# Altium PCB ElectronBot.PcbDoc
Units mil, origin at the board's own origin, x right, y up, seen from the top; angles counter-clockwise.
Board outline 1479.69 x 1548.74 mil, 2 copper layers (Top1, Bottom2), stack 42.17 mil thick; 69 components, 72 nets, 328 pads, 93 vias.
Unrouted connection lines stored in the file: 11.
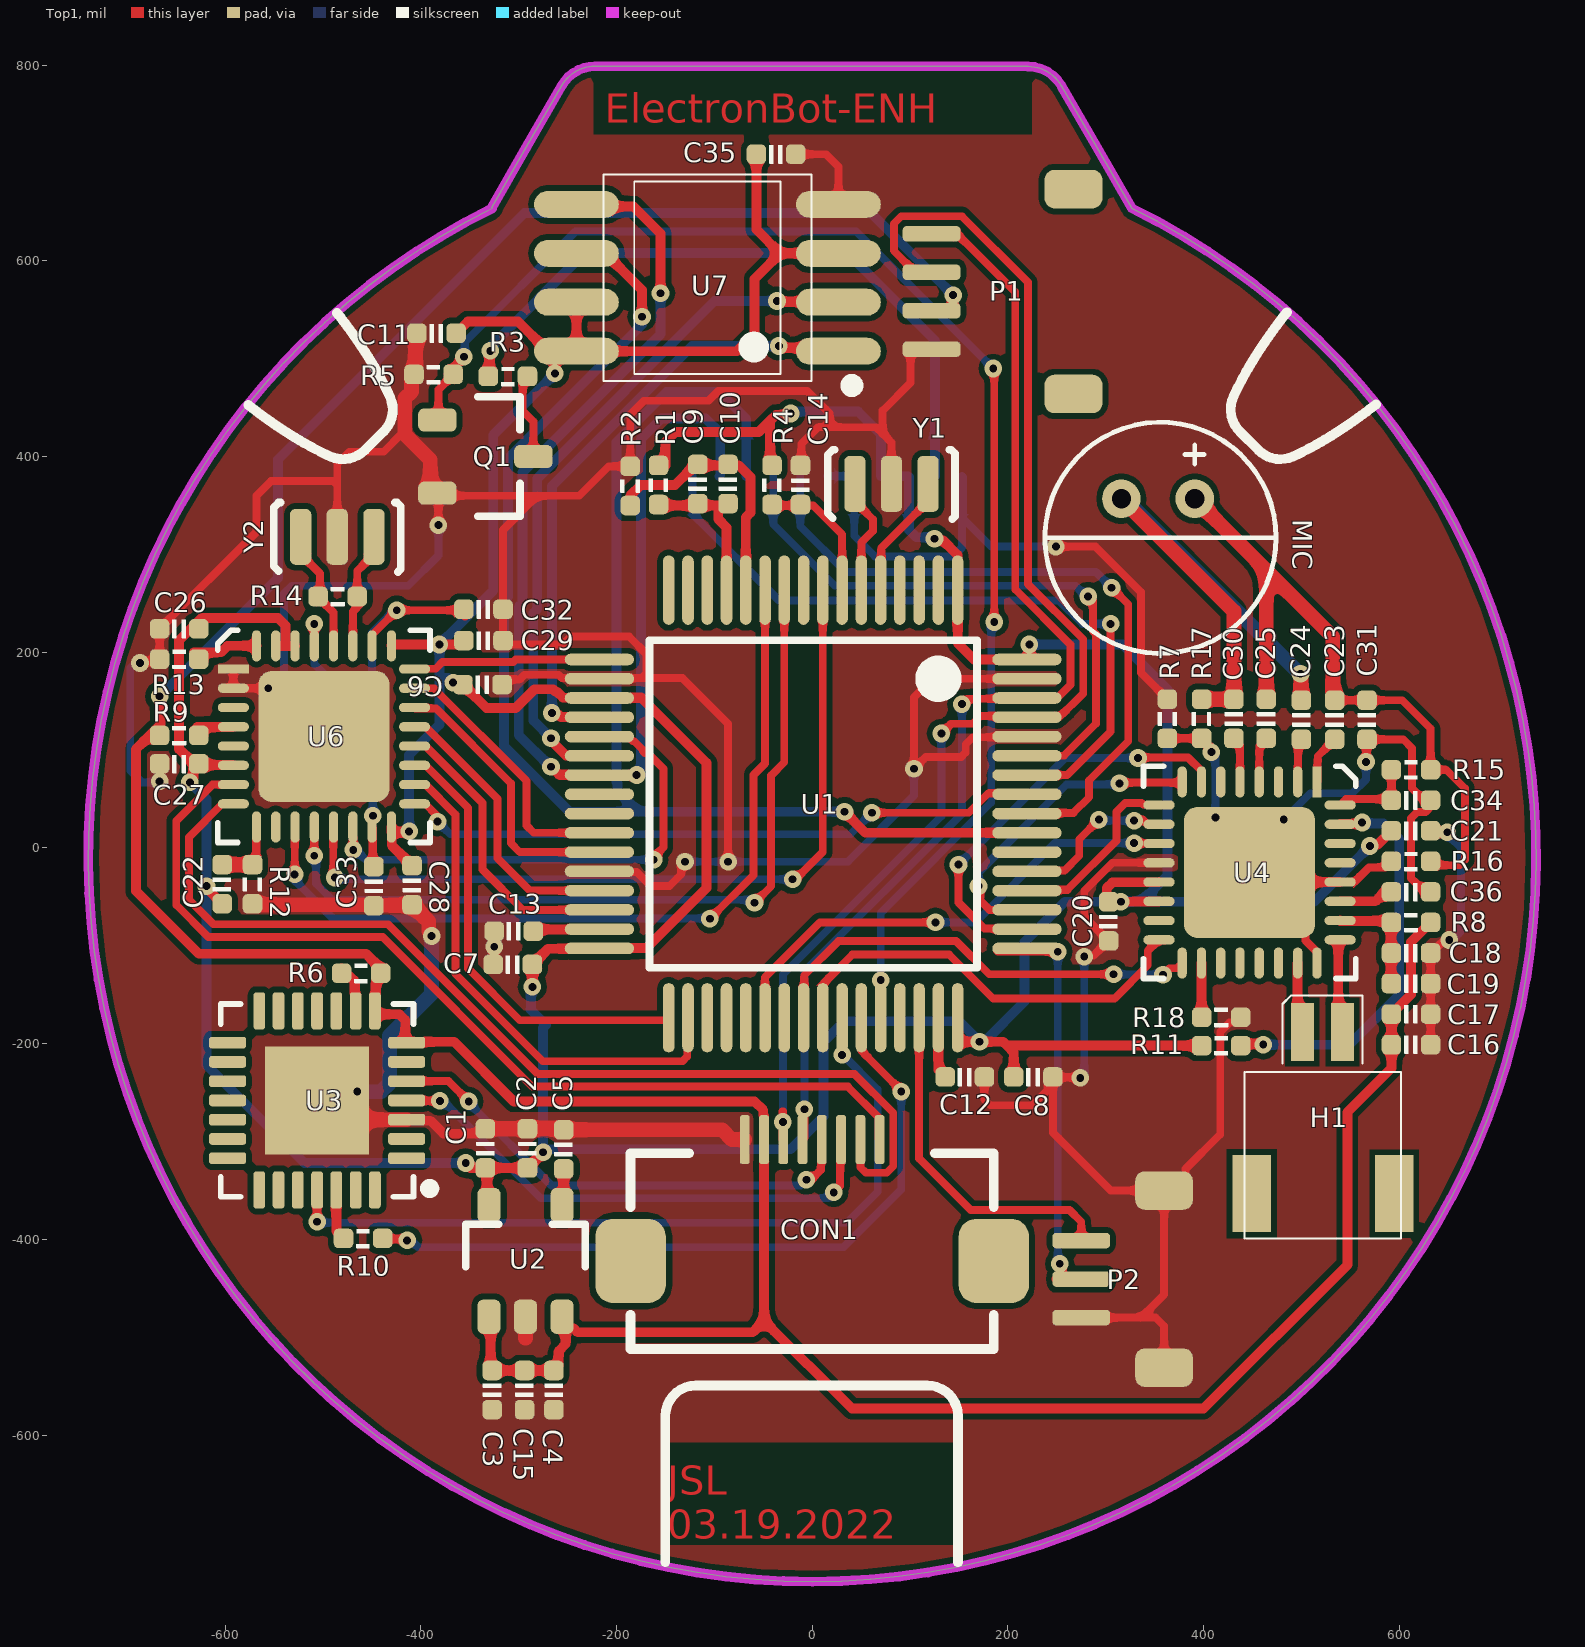
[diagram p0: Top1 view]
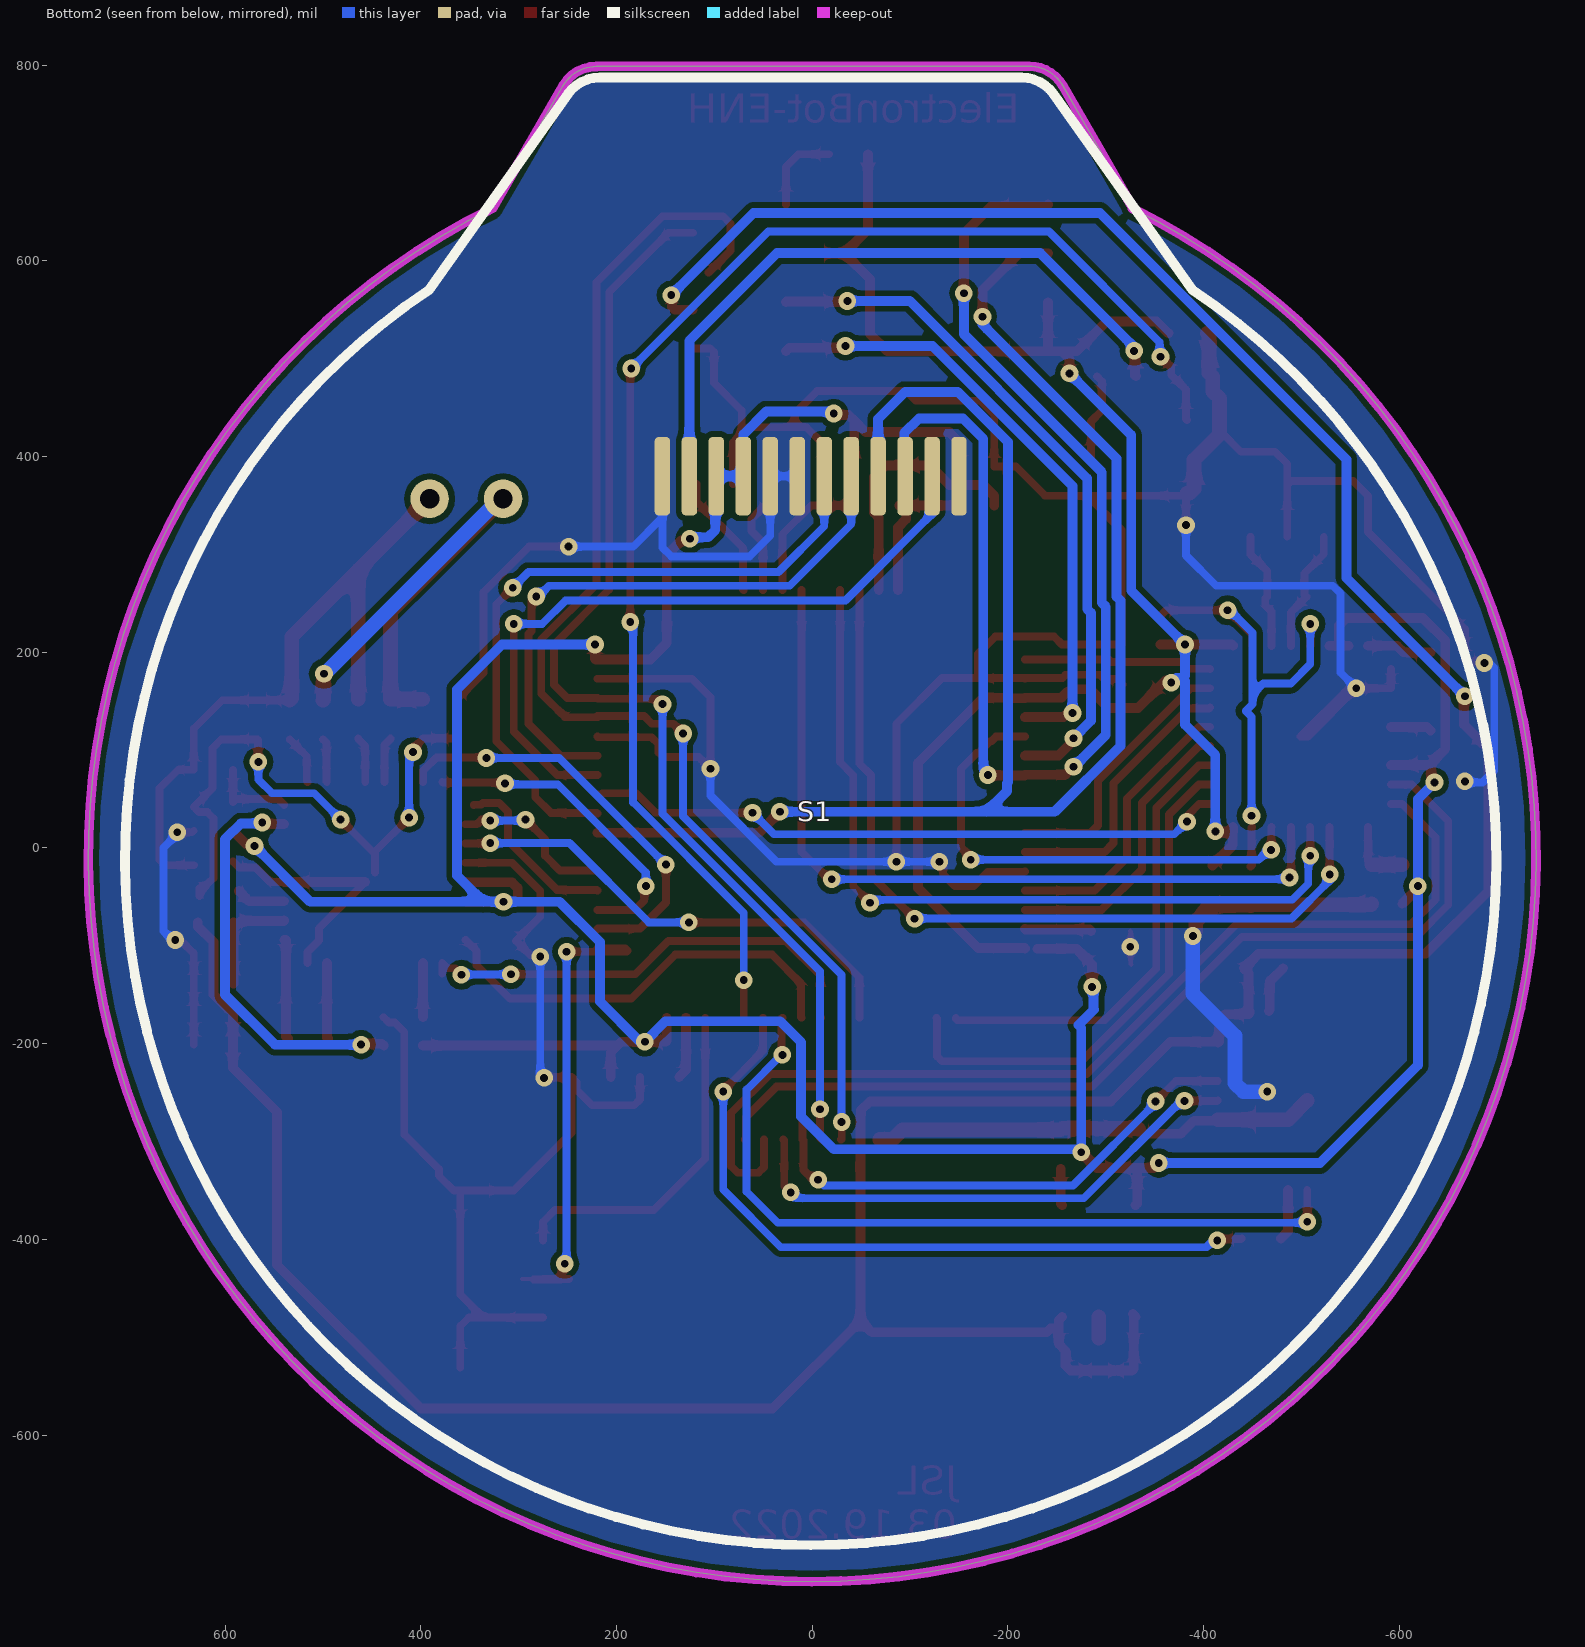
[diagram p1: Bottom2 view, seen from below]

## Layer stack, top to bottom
Top Solder: solder mask 0.4, Solder Resist, Dk 3.5
Top1: signal copper 1.4
Dielectric 1: prepreg 39.3701, PP-006, Dk 4.1
Bottom2: signal copper 1.4
Bottom Solder: solder mask 0.4, Solder Resist, Dk 3.5

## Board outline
-327.58,654.33 -292.13,716.15 -256.03,779.09 cw(c-221.88,759.5) -221.87,798.87 220.56,798.71 cw(c220.54,759.34) 254.64,779.01 290.88,716.22 326.65,654.22 326.51,653.93 cw(c0,-10)

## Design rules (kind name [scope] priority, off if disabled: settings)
Clearance Clearance_Logo [InNetClass('Logo')] p1: gap=8 ignorepadtopadclearanceinfootprint=FALSE
Clearance [All] p2: gap=5 ignorepadtopadclearanceinfootprint=FALSE
ComponentClearance [All] p1: gap=0 collisioncheckmode=3 verticalgap=0 showdistances=FALSE
DiffPairsRouting [All] p1: maxlimit=9 minlimit=9 mostfreqgap=9 toplayer_minwidth=15 toplayer_maxwidth=15 toplayer_prefwidth=15 bottomlayer_minwidth=15 bottomlayer_maxwidth=15 bottomlayer_prefwidth=15 maxuncoupledlength=500
FanoutControl Fanout_BGA [All] p1: bgadir=Out bgaviamode=Centered fanoutstyle=Auto fanoutdirection=Alternating viagrid=1 // Fanout_BGA (Default Rule)
HoleSize [All] p1: absolutevalues=TRUE maxlimit=10000 minlimit=8 maxpercent=80.000 minpercent=20.000
MinimumSolderMaskSliver [All] p1 off: minsoldermaskwidth=2
PlaneClearance [All] p1: clearance=8
PlaneConnect [All] p1: planeconnectstyle=Direct reliefexpansion=20 reliefentries=4 reliefconductorwidth=10 reliefairgap=10
PolygonConnect [All] p1: connectstyle=Direct reliefconductorwidth=10 reliefentries=4 polygonreliefangle="90 Angle" airgapwidth=10
RoutingVias [All] p1: holewidth=8 width=16 viastyle="Through Hole" minholewidth=6 minwidth=12 maxholewidth=28 maxwidth=50
SilkToSilkClearance [All] p1: silktosilkclearance=0
SilkToSolderMaskClearance [IsPad] p1: minsilkscreentomaskgap=0 clearancetoexposedcopper=TRUE
SolderMaskExpansion [All] p1: expansion=3
Width Logo [InNetClass('Logo')] p1: maxlimit=100 minlimit=0.1 preferedwidth=10
Width GND [(InNet('AGND') OR InNet('GND'))] p2: maxlimit=50 minlimit=4 preferedwidth=10
Width VCC [(InNet('VDD_SYS_3.3V') OR InNet('VDD_AV_3.3V') OR InNet('VDD_5V') OR InNet('VDD1V2-SYS') OR InNet('VDD1V1-EPHY') OR InNet('VDD-CPUX') OR InNet('VDD-CPUS') OR InNet('VDD-CPUFB') OR InNet('VCC-DRAM'))] p3: maxlimit=50 minlimit=4 preferedwidth=10
Width [All] p4: maxlimit=10000 minlimit=4 preferedwidth=4
21 further rules are at their usual default settings.

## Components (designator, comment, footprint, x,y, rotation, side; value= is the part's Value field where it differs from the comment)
C1 "0.1uF" CAP_0402 -334,-307 r270 top value=0.1u
C2 "10uF" CAP_0402 -291,-307 r270 top value=0.1u
C3 "10uF" CAP_0402 -327,-554 r90 top value=0.1u
C4 "0.1uF" CAP_0402 -264,-554 r90 top value=0.1u
C5 "10nF" CAP_0402 -254,-308 r270 top value=0.1u
C6 "0.1uF" CAP_0402 -337,167 r180 top value=0.1u
C7 "0.1uF" CAP_0402 -306,-119 r0 top value=0.1u
C8 "0.1uF" CAP_0402 226,-234 r180 top value=0.1u
C9 "0.1uF" CAP_0402 -117,372 r270 top value=0.1u
C10 "10uF" CAP_0402 -86,372 r270 top value=0.1u
C11 "0.1uF" CAP_0402 -384,526 r0 top value=0.1u
C12 "10uF" CAP_0402 156,-234 r180 top value=0.1u
C13 "10uF" CAP_0402 -305,-85 r0 top value=0.1u
C14 "0.1uF" CAP_0402 -12,371 r270 top value=0.1u
C15 "10uf" CAP_0402 -294,-554 r270 top value=0.1u
C16 "10uf" CAP_0402 612,-201 r0 top value=0.1u
C17 "0.1uF" CAP_0402 612,-169.78 r0 top value=0.1u
C18 "10uf" CAP_0402 612,-107.33 r180 top value=0.1u
C19 "0.1uF" CAP_0402 612,-138.56 r180 top value=0.1u
C20 "10uf" CAP_0402 303,-75 r90 top value=0.1u
C21 "0.1uF" CAP_0402 612,17.56 r180 top value=0.1u
C22 "10nF" CAP_0402 -603,-37 r90 top value=0.1u
C23 "1uF" CAP_0402 534,131 r90 top value=0.1u
C24 "1uF" CAP_0402 500,131 r90 top value=0.1u
C25 "1uF" CAP_0402 464,132 r90 top value=0.1u
C26 "0.1uF" CAP_0402 -647,224 r180 top value=0.1u
C27 "0.1uF" CAP_0402 -647,86 r180 top value=0.1u
C28 "0.1uF" CAP_0402 -409,-38 r270 top value=0.1u
C29 "0.1uF" CAP_0402 -336,212 r0 top value=0.1u
C30 "1uF" CAP_0402 431,132 r90 top value=0.1u
C31 "220pf" CAP_0402 567,131 r90 top value=0.1u
C32 "10uF" CAP_0402 -336,244 r0 top value=0.1u
C33 "0.1uF" CAP_0402 -448,-39 r270 top value=0.1u
C34 "10uF" CAP_0402 612,48.78 r0 top value=0.1u
C35 "0.1uF" CAP_0402 -37,709 r0 top value=0.1u
C36 "10uF" CAP_0402 612,-44.89 r0 top value=0.1u
CON1 "FFC_0.5_8" FFC_0.5_8 0,-387 r0 top
H1 "HEADER-2P" header2p_1.0 521.96,-309.06 r0 top
MIC "MIC" MIC6*2.2 356,317 r0 top (schematic designator U5)
P1 "SH1.0-4P" SH1.0-4P 122,568.69 r90 top
P2 "SH1.0-3P-STAND" SH1.0-3P-STAND 275,-440.63 r90 top
Q1 "AO3400A" SOT23-3 -334,400 r0 top
R1 "0R" RES_0402 -157,371 r90 top value=22R
R2 "0R" RES_0402 -186,370 r90 top value=22R
R3 "10R" RES_0402 -311,482 r180 top value=22R
R4 "10K" RES_0402 -41,371 r90 top value=22R
R5 "10K" RES_0402 -387,484 r0 top value=22R
R6 "10K" RES_0402 -461,-128 r180 top value=22R
R7 "0R" RES_0402 363,132 r90 top value=22R
R8 "0R" RES_0402 612,-76.11 r0 top value=22R
R9 "0R" RES_0402 -647,115 r0 top value=22R
R10 "200R" RES_0402 -459,-399 r180 top value=22R
R11 "0R" RES_0402 418,-202 r180 top value=22R
R12 "10K" RES_0402 -572,-37 r270 top value=22R
R13 "12K" RES_0402 -647,193 r180 top value=22R
R14 "1M" RES_0402 -485,257 r0 top value=22R
R15 "680R" RES_0402 612,80 r180 top value=22R
R16 "47K" RES_0402 612,-13.67 r180 top value=22R
R17 "0R" RES_0402 398,132 r270 top value=22R
R18 "10K" RES_0402 418,-173 r0 top value=22R
S1 "LCD-240x240-ROUND" LCD-240x240-ROUND 1.54,62.44 r0 bottom
U1 "STM32F405RGT6" LQFP-64_N 1,45 r270 top
U2 "LP2992 3V3" SOT23-5 -293,-420 r90 top
U3 "CP2102" QFN-28 -506,-258 r180 top value=Value
U4 "WM8978" QFN-32 447,-25 r270 top
U6 "USB3300-EZK-TR" QFN-32 -499,114 r0 top
U7 "W25Q256" flash -108,579 r180 top
Y1 "8MHz" 晶振-3P 81,372 r180 top
Y2 "24MHz" 晶振-3P -485.4,318 r180 top

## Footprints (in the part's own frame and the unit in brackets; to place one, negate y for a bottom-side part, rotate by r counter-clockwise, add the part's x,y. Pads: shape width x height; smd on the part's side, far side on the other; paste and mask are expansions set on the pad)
CAP_0402 [mil]
  rrect50% 20x20 smd: 1(-20,0) 2(20,0)
  silkscreen extent -7,-9 7,9, body extent -20,-10 20,10, height 20
FFC_0.5_8 [mil]
  rrect50% 72x86 smd: 0(-185.63,-35) 0(185.63,-35)
  rrect50% 10x50 smd: 1(-68.9,89) 2(-49.21,89) 3(-29.53,89) 4(-9.84,89) 5(9.84,89) 6(29.53,89) 7(49.21,89) 8(68.9,89)
  silkscreen extent -186,-125 186,75, body extent -187,-124 187,87, height 82
flash [mm]
  oval 2.2x0.7 smd: 1(-3.424,1.809) 2(-3.424,0.539) 3(-3.424,-0.731) 4(-3.424,-2.001) 5(3.376,-2.001) 6(3.376,-0.731) 7(3.376,0.539) 8(3.376,1.809)
  silkscreen extent -3.92,-2.77 2.68,2.85
header2p_1.0 [mm]
  rect 1x2 smd: 0(-1.85,-1.125) 0(1.85,-1.125)
  rect 0.6x1.5 smd: 1(-0.532,3.075) 2(0.509,3.075)
  silkscreen extent -2.03,-2.29 2.03,4.03
LCD-240x240-ROUND [mm]
  rrect50% 0.4x2.032 smd: 1(3.85,-8.066) 2(3.15,-8.066) 3(2.45,-8.066) 4(1.75,-8.066) 5(1.05,-8.066) 6(0.35,-8.066) 7(-0.35,-8.066) 8(-1.05,-8.066) 9(-1.75,-8.066) 10(-2.45,-8.066) 11(-3.15,-8.066) 12(-3.85,-8.066)
  silkscreen extent -17.8,-18.42 17.8,19.69, body extent -17.8,-18.41 17.8,19.68
LQFP-64_N [mm]
  oval 1.8x0.3 smd: 1(-5.55,3.75) 2(-5.55,3.25) 3(-5.55,2.75) 4(-5.55,2.25) 5(-5.55,1.75) 6(-5.55,1.25) 7(-5.55,0.75) 8(-5.55,0.25) 9(-5.55,-0.25) 10(-5.55,-0.75) 11(-5.55,-1.25) 12(-5.55,-1.75) 13(-5.55,-2.25) 14(-5.55,-2.75) 15(-5.55,-3.25) 16(-5.55,-3.75) 33(5.55,-3.75) 34(5.55,-3.25) 35(5.55,-2.75) 36(5.55,-2.25) 37(5.55,-1.75) 38(5.55,-1.25) 39(5.55,-0.75) 40(5.55,-0.25) 41(5.55,0.25) 42(5.55,0.75) 43(5.55,1.25) 44(5.55,1.75) 45(5.55,2.25) 46(5.55,2.75) 47(5.55,3.25) 48(5.55,3.75)
  oval 0.3x1.8 smd: 17(-3.75,-5.55) 18(-3.25,-5.55) 19(-2.75,-5.55) 20(-2.25,-5.55) 21(-1.75,-5.55) 22(-1.25,-5.55) 23(-0.75,-5.55) 24(-0.25,-5.55) 25(0.25,-5.55) 26(0.75,-5.55) 27(1.25,-5.55) 28(1.75,-5.55) 29(2.25,-5.55) 30(2.75,-5.55) 31(3.25,-5.55) 32(3.75,-5.55) 49(3.75,5.55) 50(3.25,5.55) 51(2.75,5.55) 52(2.25,5.55) 53(1.75,5.55) 54(1.25,5.55) 55(0.75,5.55) 56(0.25,5.55) 57(-0.25,5.55) 58(-0.75,5.55) 59(-1.25,5.55) 60(-1.75,5.55) 61(-2.25,5.55) 62(-2.75,5.55) 63(-3.25,5.55) 64(-3.75,5.55)
  silkscreen extent -4.25,-4.25 4.25,4.25, body extent -5.99,-5.99 5.98,5.98, height 1.6
MIC6*2.2 [mm]
  round 1 hole 0.5: 1(0.889,1.016) 2(-1.016,1.016)
  silkscreen extent -3,-3 3,3
QFN-28 [mil]
  rrect50% 38x12 smd mask+5: 1(-91.5,59.06) 2(-91.5,39.37) 3(-91.5,19.68) 4(-91.5,0) 5(-91.5,-19.68) 6(-91.5,-39.37) 7(-91.5,-59.06) 15(91.5,-59.06) 16(91.5,-39.37) 17(91.5,-19.68) 18(91.5,0) 19(91.5,19.68) 20(91.5,39.37) 21(91.5,59.06)
  rrect50% 12x38 smd mask+5: 8(-59.06,-91.5) 9(-39.37,-91.5) 10(-19.69,-91.5) 11(0,-91.5) 12(19.68,-91.5) 13(39.37,-91.5) 14(59.06,-91.5) 22(59.06,91.5) 23(39.37,91.5) 24(19.68,91.5) 25(0,91.5) 26(-19.69,91.5) 27(-39.37,91.5) 28(-59.06,91.5)
  rect 106.3x110.24 smd: 29(0,0)
  silkscreen extent -120,-99 99,99, body extent -99,-99 98,98, height 35
QFN-32 [mm]
  rect 0.81x0.239 smd paste+0 mask+0: 1(-2.351,1.75)
  rrect100% 0.81x0.239 smd paste+0 mask+0: 2(-2.351,1.25) 3(-2.351,0.75) 4(-2.351,0.25) 5(-2.351,-0.25) 6(-2.351,-0.75) 7(-2.351,-1.25) 8(-2.351,-1.75) 17(2.351,-1.75) 18(2.351,-1.25) 19(2.351,-0.75) 20(2.351,-0.25) 21(2.351,0.25) 22(2.351,0.75) 23(2.351,1.25) 24(2.351,1.75)
  rrect100% 0.239x0.81 smd paste+0 mask+0: 9(-1.75,-2.351) 10(-1.25,-2.351) 11(-0.75,-2.351) 12(-0.25,-2.351) 13(0.25,-2.351) 14(0.75,-2.351) 15(1.25,-2.351) 16(1.75,-2.351) 25(1.75,2.351) 26(1.25,2.351) 27(0.75,2.351) 28(0.25,2.351) 29(-0.25,2.351) 30(-0.75,2.351) 31(-1.25,2.351) 32(-1.75,2.351)
  rrect20% 3.4x3.4 smd paste-1000 mask+0: 33(0,0)
  silkscreen extent -2.76,-2.76 2.76,2.76, body extent -2.51,-2.51 2.51,2.51, height 0.85
RES_0402 [mil]
  rrect50% 20x20 smd: 1(-20,0) 2(20,0)
  silkscreen extent -7,-10 7,10, body extent -20,-10 20,10, height 14
SH1.0-3P-STAND [mm]
  rrect50% 0.4x1.5 smd: 1(-1,0) 2(0,0) 3(1,0)
  rrect50% 1x1.5 smd: SH1(-2.3,-2.15) SH2(2.3,-2.15)
  body extent -2.5,-2.91 2.5,0.69, height 4.25
SH1.0-4P [mm]
  rrect50% 0.4x1.5 smd: 1(-1.5,0) 2(-0.5,0) 3(0.5,0) 4(1.5,0)
  rrect50% 1x1.5 smd: SH1(-2.659,-3.683) SH2(2.659,-3.683)
  body extent -3,-4.42 3,0.54, height 3.14
SOT23-3 [mm]
  rrect50% 1x0.6 smd: 1(-1.246,0.95) 2(-1.246,-0.95) 3(1.246,0)
  silkscreen extent -0.2,-1.55 0.9,1.55, body extent -1.3,-1.45 1.5,1.45, height 1.2
SOT23-5 [mm]
  rrect50% 0.889x0.6 smd: 1(-1.5,0.95) 2(-1.5,0) 3(-1.5,-0.95) 4(1.396,-0.95) 5(1.396,0.95)
  silkscreen extent -0.2,-1.55 0.9,1.55, body extent -1.48,-1.45 1.32,1.45, height 1.2
晶振-3P [mm]
  rrect50% 0.55x1.45 smd: 1(-0.95,0) 2(0,0) 3(0.95,0)
  silkscreen extent -1.65,-0.89 1.65,0.91, body extent -1.6,-0.89 1.65,0.89, height 0.7

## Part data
C1 C2 C3 C4 C5 C6 C7 C8 C9 C10 C11 C12 C13 C14 C15 C16 C17 C18 C19 C20 C21 C22 C23 C24 C25 C26 C27 C28 C29 C30 C31 C32 C33 C34 C35 C36: library part 电容-0402, "Capacitor"
CON1: "FFC"
P2: "Header"
Q1: "N-MOS"
R1 R2 R3 R4 R5 R6 R7 R8 R9 R10 R11 R12 R13 R14 R15 R16 R17 R18: library part 电阻-0402, "Resistor"
S1: "显示屏"
U1: "ARM Cortex-M4 32-bit MCU+FPU, 210 DMIPS, 1024 kB Flash, 192 kB Internal RAM, 51 I/Os, 64-pin LQFP, -40 to 85 degC, Tray", I/Os (High Current)=51, Manufacturer=STMicroelectronics, Operating Frequency(F) (Processor speed) (MHz)=168, Supplier Part Number 1=497-11767-ND, Supply Voltage(Vcc) max (V)=3.6, Supply Voltage(Vcc) min (V)=1.8
U2: library part LP2992, "LDO"
U3: "USBתTTL"
U7: "W25Q256-QFN8"
Y1 Y2: library part 晶振-3Pin, "村田贴片"

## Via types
v1: diameter 18, hole 8, Top1 to Bottom2, 93 vias

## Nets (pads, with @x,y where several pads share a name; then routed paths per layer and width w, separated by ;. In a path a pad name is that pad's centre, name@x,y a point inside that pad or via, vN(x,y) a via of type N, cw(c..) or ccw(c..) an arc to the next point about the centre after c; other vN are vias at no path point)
AGND: C9.1 C10.1 R2.1 U1.12 | length 258.8
  Top1 w10: R2.1 -186,360 -175,371 -140.14,371 -120.14,391 C10.1@-96,391 ; C10.1 -85,391 -75,391 -63,379 -63,342.71 -67.9,337.81 U1.12
AVCC: C9.2 C10.2 R1.1 U1.13 | length 151
  Top1 w10: R1.1@-150,350 C10.2@-96,350 ; C10.2@-89,350 C10.2@-96,350 ; U1.13 -87.58,327.58 -96,336 C10.2@-96,350
FLASH_CS_1: U1.20 U7.1 | length 636.5
  Top1 w10: v1(-266,138) -264.47,136.47 -259.47,136.47 -256.93,133.93 -217.85,133.93 U1.20 ; v1(-34,513) -31.84,513 -29.96,511.12 23.44,511.12 U7.1
  Bottom2 w10: v1(-266,138) -266,370 -123,513 v1(-34,513)
FLASH_MISO_1: U1.22 U7.2 | length 716.4
  Top1 w10: v1(-267,112.13) -267,109.87 -251.69,94.56 -217.85,94.56 U1.22 ; v1(-36,559) -35.38,558.38 26.18,558.38 U7.2
  Bottom2 w10: v1(-267,112.13) -285,130.13 -285,240.36 -281,244.36 -281,377.79 -99.79,559 v1(-36,559)
FLASH_MOSI_1: S1.10 U1.23 U7.5 | length 1299.9
  Top1 w10: v1(-267,83) -258.87,74.87 -217.85,74.87 U1.23 -217.16,74.18 -177.07,74.18 -177.07,74.53 -177.07,75 -177.54,74.53 v1(-179.51,74.53) ; U7.5 -238.69,655.54 -182.61,655.54 -155,627.94 v1(-155,567)
  Bottom2 w10: v1(-267,83) -267.46,83 -300,115.54 -300,246.57 -296,250.57 -296,384 -155,525 v1(-155,567) ; v1(-179.51,74.53) -179.51,76.49 -174.86,81.14 -174.86,418.14 -154,439 -109,439 -94,424 -94,380.91 S1.10
FLASH_SCK_1: S1.9 U1.55 U7.6 | length 1788.8
  Top1 w10: U7.6 -211.39,607.76 -174,570.38 v1(-174,543) ; v1(33,37) 54.53,15.47 U1.55
  Bottom2 w10: v1(-174,543) -174,535 -311,398 -311,256.79 -315,252.79 -315,104.13 -247.87,37 -178,37 ; S1.9 -67.35,438.35 -95,466 -148.79,466 -200,414.79 -200,67.13 -199,66.13 -199,58 -178,37 ; v1(33,37) -178,37
GND: C1.1 C2.1 C3.1 C4.1 C5.1 C6.1 C7.1 C8.1 C11.1 C12.1 C13.1 C14.1 C15.2 C16.2 C17.2 C18.1 C19.1 C20.1 C21.1 C26.2 C27.2 C28.2 C29.2 C32.2 C33.2 C35.2 CON1.1 P1.1 P2.1 P2.SH1 P2.SH2 Q1.2 R2.2 R5.1 R7.2 R12.2 R13.2 R18.2 S1.1 S1.5 S1.6 S1.12 U1.18 U1.28 U1.60 U1.63 U2.2 U3.3 U3.29 U4.12 U6.1 U6.2 U6.33 U7.4 Y1.2 Y2.2 | length 6690.4
  Top1 w5: C1.1 C1.1@-333.5,-287.5 ; C7.1 -325.5,-118.5 -325.5,-85.5 C13.1
  Top1 w8: v1(-687,189) -685.09,190.91 -669.09,190.91 R13.2 C26.2 -568,323 -568,360 -553,375 -489.4,375 -485.4,371 ; U6.1 U6.2 v1(-556,163.21) ; Y2.2 -485.4,371 ; -420,423 -438,405 -473,405 -485.4,392.6 -485.4,371 ; Q1.2 Q1.2@-382,361.54 ; v1(-382,330) Q1.2@-382,361.54 ; C6.1 -311.62,172.38 -298.62,172.38 -294,177 -259,177 -255.68,173.68 -218.23,173.68 U1.18 -216.77,173.68 -174.32,173.68 ; U1.28 -216.77,-24.63 -179.37,-24.63 -165,-39 -146,-39 -134,-27 -134,-18 v1(-130,-14) ; v1(-86,-14) -86,127 -132.68,173.68 -174.32,173.68 ; C35.2 14,709 26.8,696.2 U7.4 ; C14.1 -11,392 -11,413 6,430 18,430 ; Y1.2 81,414.24 72,423.24 ; P1.1@122,510.63 104.28,510.63 100.41,506.76 100.41,475.41 72,447 72,423.24 ; C12.1 176,-257 182,-263 225,-263 240.62,-247.38 240.62,-239.38 C8.1 ; U1.60 218.77,113.17 164.17,113.17 157,106 157,97.69 152.31,93 116,93 v1(104,81) 104,154 122.95,172.95 U1.63 ; C8.1@248,-238 C8.1@246,-236 ; v1(249,308) 289.46,308 336,261.46 336,179 R7.2 ; v1(274,-235) 273.5,-234.5 246.5,-234.5 C8.1 ; P2.1 336,-480 ; v1(278,-111) 279,-110 287.46,-110 302.46,-95 C20.1@302.46,-94.46 ; C20.1 C20.1@302.46,-94.46 ; U4.12 306.84,-15.16 278,-44 278,-70 C20.1@302.46,-94.46 ; P2.SH1 359.65,-488.65 351,-480 336,-480 ; R18.2 432.62,-178.38 426.62,-178.38 417,-188 417,-292.73 381.57,-328.16 381.57,-334.84 366.33,-350.08 P2.SH2 ; C16.2 C17.2 C19.1 C18.1 632.54,-107.33 643.96,-95.91 649.09,-95.91 v1(651,-94) ; C21.1 633.56,16 v1(649,16) ; v1(-556,163.21) -548.21,163.21 U6.33 -506.79,114 v1(-556,163.21) ; Q1.2@-382,361.54 -380.46,360 -281,360 ; -281,360 -238,360 -208,390 R2.2 -186,443 -172,457 -106,457 -96,467 -5,467 18,444 18,430 ; -281,360 -316,325 -316,208 -255.23,208 -247.23,216 -187,216 -169.31,198.31 -169.31,178.69 -174.32,173.68 ; 18,430 65.24,430 72,423.24 ; C8.1@246,-236 246,-291 305.08,-350.08 P2.SH2 ; C8.1@246,-236 C8.1 ; 336,-480 359.65,-456.35 P2.SH2
  Top1 w10: U3.3 -413.5,-278.68 -390.31,-278.68 -377,-292 -339,-292 C1.1
  Top1 w15: R12.2 -571,-58 -449,-58 C33.2 -447.5,-58.5 -409.5,-58.5 C28.2 -392,-75 -392,-85 -389.57,-87.43 -389.57,-89.43 v1(-389,-90) ; U3.29 -486.31,-277.68 U3.3 ; C11.1 -405.5,524.5 -405.5,485.5 R5.1 -409.5,481.5 -409.5,466.5 -416.33,459.67 -416.33,423 -390.24,396.91 -390.24,366.91 -385.93,362.6 Q1.2 ; C1.1@-333.5,-287.5 -333,-287 -291.5,-287 -291,-287.5 -290,-286.5 -255.5,-286.5 C5.1@-254.5,-287.5 ; -293,-501 U2.2 ; C5.1 -92,-288 -82,-298 CON1.1
  Bottom2 w8: v1(-687,189) -692,189 -697,184 -697,79 -685,67 -668,67 v1(-667,68) ; v1(-556,163.21) -540,179.21 -540,260 -532,268 -413,268 -382,299 v1(-382,330) ; v1(-130,-14) v1(-86,-14) 36.46,-14 104,53.54 v1(104,81) ; S1.6 S1.5 42.88,319.12 64,298 144,298 153.12,307.12 S1.1 154,379.12 154,337 183,308 v1(249,308) ; v1(274,-235) 274,-234 278,-230 v1(278,-111) ; v1(649,16) 649,14.3 663,0.3 663,-85 655,-93 652,-93 v1(651,-94)
  Bottom2 w15: v1(-465,-249) -440.79,-249 -432,-240.21 -432,-192 -389,-149 v1(-389,-90)
  other v1: -325,-101
GND_ANALOG_1: C31.1 C34.2 C36.2 R7.1 R16.2 R17.2 U4.24 U4.28 U4.33 | length 867
  Top1 w8: R7.1 R17.2 398,111.46 406.09,103.37 406.09,99.91 v1(408,98) ; v1(412,31) 447,-4 U4.33@447,-6 ; U4.33 U4.33@447,-6 ; U4.33@456.84,-34.84 504.14,-82.14 504.14,-94.47 515.9,-106.23 U4.24 ; v1(482,29) U4.33@447,-6 ; U4.28 554.16,-34.84 569,-20 585.67,-20 R16.2 ; v1(566,88) 566.5,88.5 566.5,110.5 C31.1 604,111 613,102 613,61 632,42 626.62,36.62 618.19,36.62 612,30.43 612,-30.96 C36.2@626.12,-45.08 ; C36.2@626.12,-49.05 C36.2@626.12,-45.08 ; C36.2@626.12,-41.12 C36.2@626.12,-45.08
  Top1 w10: U4.33@456.84,-34.84 U4.28
  Bottom2 w8: v1(408,98) 412,94 v1(412,31) ; v1(482,29) 509,56 552,56 566,70 v1(566,88)
I2C3_SCL_1: U1.41 U4.16 | length 445.1
  Top1 w8: U1.41 11.57,-172.77 11.57,-138.43 41,-109 140,-109 185,-154 308.93,-154 343,-119.93 343,-105.33 U4.16 354.01,-93.9 U4.16@352.46,-95.45
I2C3_SDA_1: U1.40 U4.17 | length 474.3
  Top1 w8: U1.40 -8.11,-172.77 -8.11,-130.11 27,-95 147,-95 181,-129 v1(308,-129) ; v1(358.5,-129.5) 365.11,-122.89 372.78,-122.89 U4.17 U4.17@378.1,-128.21
  Bottom2 w8: v1(308,-129) 308.25,-129.25 358.25,-129.25 v1(358.5,-129.5)
I2C_SCL_1: CON1.3 P1.3 U1.61 | length 1338.2
  Top1 w8: v1(-30,-280) -30,-269 -30.26,-269 -30.26,-297.26 CON1.3 ; P1.3@106,588 83.47,610.53 83.47,638.04 91.05,645.61 152.95,645.61 220.47,578.09 220.47,269.69 276.94,213.22 276.94,157.97 252.55,133.58 U1.61 ; v1(132,117) 142,127 164,127 172,135 U1.61@219.5,135
  Bottom2 w8: v1(-30,-280) -30,-129.62 132,32.38 v1(132,117)
I2C_SDA_1: CON1.4 P1.4 U1.62 | length 1167
  Top1 w8: CON1.4 -8,-296.16 v1(-8,-267) ; P1.4@122,628.74 146.97,628.74 207.47,568.24 207.47,264.3 263.94,207.84 263.94,166.78 250.43,153.27 U1.62 218.77,152.54 158.54,152.54 v1(153,147)
  Bottom2 w8: v1(-8,-267) -8,-126 153,35 v1(153,147)
I2S3_CK_1: U1.51 U4.8 | length 328.7
  Top1 w8: v1(170,-39) 171.65,-39 171.65,-53.65 181.27,-63.27 U1.51 ; v1(314,66) 314.78,66.78 377.45,66.78 378.1,67.44 U4.8
  Bottom2 w8: v1(170,-39) 170,-25 260,65 313,65 v1(314,66)
I2S3_EXT_SD_1: U1.52 U4.9 | length 181.8
  Top1 w8: U1.52 220.23,-42.85 260.76,-42.85 311,7.38 311,37 320,46 336.46,46 338.29,44.17 345.83,44.17 U4.9@346,44
I2S3_MCLK_1: U1.38 U4.11 | length 512.5
  Top1 w8: U1.38 -48.21,-132.21 8,-76 v1(126,-76) ; v1(329,5) 329.24,4.76 354.19,4.76 U4.11 U4.11@342.87,4.53
  Bottom2 w8: v1(126,-76) 167,-76 248,5 v1(329,5)
I2S3_SD_1: U1.53 U4.10 | length 169.8
  Top1 w8: U1.53 220.23,-23.17 257.83,-23.17 273,-8 273,9 v1(293,29) ; v1(329,28) 330.2,29.2 337.83,29.2 342.82,24.21 U4.10
  Bottom2 w8: v1(293,29) 294,28 v1(329,28)
I2S3_WS_1: U1.50 U4.7 | length 432.1
  Top1 w8: v1@151,-17 v1(149.5,-17) 149.5,-55.79 175.93,-82.22 218.77,-82.22 U1.50 ; v1(333,92) 333.51,92.51 384.08,92.51 397.79,78.8 U4.7
  Bottom2 w8: v1(149.5,-17) 258.5,92 v1(333,92)
LCD_BL_1: Q1.1 R5.2 U1.44 | length 1445.4
  Top1 w8: Q1.1 -382,438.46 -382,468.46 -367,483.46 R5.2 -367,491 v1(-356,502) ; U1.44 70,-173.61 v1(70,-135) ; v1(185,490) 186,489 v1(186,231)
  Bottom2 w8: v1(-356,502) -356,503 -355,504 -355,517 -242,630 45,630 v1@183,492 ; v1(70,-135) 70,-66.38 183,46.62 183,225.29 186,228.29 v1(186,231)
LCD_CS_1: S1.8 U1.59 | length 618.9
  Top1 w8: U1.59 257.21,94.21 289.94,126.94 289.94,218.61 286.94,221.61 286.94,250.06 282,255 v1(282,257)
  Bottom2 w8: S1.8 -39.8,330.8 23,268 269,268 280,257 v1(282,257)
LCD_DC_1: S1.7 U1.56 | length 703.5
  Top1 w8: U1.56 220.23,35.89 266.89,35.89 283,52 283,69.13 323,109.13 323,249 v1(306,266)
  Bottom2 w8: S1.7 -12.24,328.78 34.54,282 290,282 v1(306,266)
LCD_LEDK_1: R3.2 S1.2 | length 700.7
  Top1 w10: R3.2 -330,483 -330,507 v1(-329,508)
  Bottom2 w10: v1(-329,508) -329,512 -233,608 36,608 125.56,518.44 S1.2
LCD_RST_1: S1.11 U1.58 | length 726.5
  Top1 w8: U1.58 260.53,74.53 305,119 v1(305,229)
  Bottom2 w8: S1.11 -122.47,341.47 -34,253 252,253 276,229 v1(305,229)
NetC5_2: C5.2 U2.4 | length 37.7
  Top1 w10: U2.4 -254,-363.46 C5.2
NetC12_2: C12.2 U1.47 | length 63.4
  Top1 w10: U1.47 128.95,-226.95 C12.2
NetC13_2: C13.2 U1.31 | length 68.3
  Top1 w10: C13.2 -283.3,-83.3 -217.85,-83.3 U1.31
NetC14_2: C14.2 R4.1 U1.7 | length 131.7
  Top1 w8: R4.1@-32,350 1,350 30.53,320.47 U1.7
NetC18_2: C18.2 C19.2 R8.1 U4.26 | length 118.5
  Top1 w10: U4.26 539.86,-74.5 583.5,-74.5 R8.1@591.5,-82.5 ; C19.2@591.5,-138.56 591.5,-107.33 R8.1@591.5,-82.5 ; R8.1@591.5,-76.11 R8.1@591.5,-82.5 ; R8.1@592,-83 R8.1@591.5,-82.5
NetC22_2: C22.2 R12.1 U6.9 | length 71.1
  Top1 w8: R12.1 -568.17,-13.17 -568.17,21.16 U6.9
  Top1 w15: C22.2 R12.1
NetC23_1: C23.1 U4.1 | length 50.9
  Top1 w8: U4.1 516.61,68.28 516.61,93.61 C23.1
NetC23_2: C23.2 C25.2 C31.2 MIC.1 R15.1 R16.1 | length 702.9
  Top1 w8: C23.2 C31.2 603,151 632,122 R15.1 648,80 667,61 667,-12 661.43,-17.57 R16.1@631.5,-17.57
  Top1 w15: MIC.1 464,284 ; C25.2 464,284 ; C23.2 532,153 532,216 464,284
NetC24_1: C24.1 U4.2 | length 45
  Top1 w8: U4.2 496.48,67.84 496.48,107.48 C24.1
NetC24_2: C24.2 C30.2 MIC.2 R17.1 | length 570.2
  Top1 w15: MIC.2 431,242 C30.2 R17.1 ; v1(499,178) 499.5,177.5 499.5,151.5 C24.2
  Bottom2 w15: MIC.2 319.19,357 498.19,178 v1(499,178)
NetC25_1: C25.1 U4.4 | length 47.4
  Top1 w8: U4.4 456.84,104.3 464,111.46 C25.1
NetC30_1: C30.1 U4.5 | length 47
  Top1 w8: C30.1 431,111.46 437.16,105.3 U4.5
NetC32_1: C32.1 C33.1 U6.15 U6.26 U6.29 | length 534.7
  Top1 w8: v1(-509,229) -512,229 -509.11,226.11 -509.11,206.84 U6.29 ; U6.15 -449,20.64 -449,-12.16 -449.52,-12.68 -449.52,-17.48 C33.1 ; U6.26 -449.79,217.8 v1(-424.58,243) -361.64,243 C32.1@-355,236.36
  Bottom2 w8: v1(-509,229) -509,188 -489,168 -461,168 -450,157 ; v1@-451.91,35.91 v1(-449,33) ; v1(-424.58,243) -425.58,242 -428,242 -450,220 -450,157 ; -450,157 -450,147 -443,140 -449,134 v1(-449,33) ; v1(-449,33) -448,34 v1(-449,33)
NetC34_1: C34.1 R15.2 U4.32 | length 89.2
  Top1 w8: U4.32 545.67,50 589,50 592,47 C34.1 R15.2
NetC36_1: C36.1 U4.27 | length 50.8
  Top1 w10: U4.27 575.47,-54.53 C36.1@586,-44
NetH1_1: H1.1 U4.23 | length 77.6
  Top1 w10: H1.1@494.87,-194.65 495.92,-193.6 495.92,-117.86 U4.23
NetH1_2: H1.2 U4.25 | length 103.2
  Top1 w10: H1.2@535.87,-194.65 537.72,-192.8 537.72,-94.19 538.01,-93.9 U4.25
NetQ1_3: Q1.3 R3.1 | length 88.7
  Top1 w8: R3.1 -296,477 -296,447 -284.94,435.94 Q1.3
NetR6_2: R6.2 U3.9 | length 49.5
  Top1 w10: R6.2@-481,-123 -467.63,-136.37 -467.63,-165.5 U3.9
NetR9_2: R9.2 U6.4 | length 42
  Top1 w10: R9.2@-632,120 -628.45,123.55 -591.86,123.55 U6.4
NetR10_2: R10.2 U3.26 | length 52.5
  Top1 w10: U3.26 -486.31,-391.68 R10.2
NetR11_1: R11.1 U4.31 | length 411.6
  Top1 w10: R11.1 440,-200 456,-200 457,-201 v1(461,-201) ; U4.31 539.86,24.5 560.5,24.5 v1(562,26)
  Bottom2 w10: v1(461,-201) 549,-201 600,-150 600,9 584,25 563,25 v1(562,26)
NetR13_1: R13.1 U6.32 | length 66.8
  Top1 w10: R13.1@-632,200 -604.14,200 -597.57,206.57 U6.32
NetR14_1: R14.1 U6.28 Y2.3 | length 127
  Top1 w8: Y2.3 -522.8,300.28 -503,280.48 -503,259 R14.1 -505,256.46 -489.16,240.62 U6.28
NetR14_2: R14.2 U6.27 Y2.1 | length 122
  Top1 w8: U6.27 -469.47,241.73 -463,248.2 -463,255 R14.2 -465,283 -448,300 Y2.1
NetR18_1: R18.1 U4.18 | length 55.5
  Top1 w10: U4.18 397.89,-117.68 397.89,-172.89 R18.1
NetU1_5: U1.5 Y1.1 | length 128.6
  Top1 w8: U1.5 70.63,264.23 70.63,306.51 118.4,354.28 Y1.1
NetU1_6: U1.6 Y1.3 | length 121
  Top1 w8: Y1.3 43.6,354.28 62,335.88 62,324 50.21,312.21 U1.6
SWCLK_1: P2.2 U1.49 | length 511
  Top1 w4: P2.2 P2.2@296.65,-440.63
  Top1 w8: U1.49@191.37,-103 U1.49@190.65,-103 ; U1.49 191.01,-102.64 U1.49@190.65,-103 ; P2.2@248.7,-440.63 P2.2@257,-440.63 ; v1(251,-106) 189.65,-106 188.65,-105 U1.49@190.65,-103 ; v1(253,-425) 253,-432 P2.2@261.63,-440.63 ; P2.2 P2.2@261.63,-440.63 ; P2.2@285,-441 P2.2@262,-441 ; P2.2@257,-440.63 P2.2@261.63,-440.63 ; P2.2@257,-440.63 257.37,-441 P2.2@262,-441 ; P2.2@261.63,-440.63 P2.2@262,-441
  Bottom2 w8: v1(251,-106) 251,-423 v1(253,-425)
SWDIO_1: P2.3 U1.46 | length 355.6
  Top1 w8: U1.46 109.27,-317.27 162,-370 263,-370 275,-382 P2.3
UART_RX_1: R10.1 U1.43 | length 751.1
  Top1 w8: R10.1 -438.5,-399.5 -414.5,-399.5 -414,-400 v1(-414,-401) ; U1.43 50.21,-207.21 91,-248 v1(91,-249)
  Bottom2 w8: v1(-414,-401) -410,-401 -403,-408 32,-408 91,-349 v1(91,-249)
UART_TX_1: U1.42 U3.25 | length 813.1
  Top1 w8: v1(-506,-382) U3.25 ; v1(30.53,-211.5) 31.26,-210.74 31.26,-174.23 U1.42
  Bottom2 w8: v1(-506,-382) -504,-382 -503,-383 35.31,-383 67,-351.31 67,-247 31.5,-211.5 v1(30.53,-211.5)
USB_CLK_1: U1.21 U6.14 | length 511.9
  Top1 w8: U6.14 -469.2,21.16 -469.2,-1.8 v1(-469,-2) ; U1.21 -187.98,113.9 -183.2,109.12 -181.8,109.12 -173.07,100.39 -173.07,98.99 -171.18,97.11 -168.06,97.11 -152,81.04 -152,0.71 -162,-9.29 v1(-162,-12)
  Bottom2 w8: v1(-469,-2) -466.29,-2 -465.29,-3 -456.29,-12 v1(-162,-12)
USB_DATA0_1: U1.17 U6.24 | length 193
  Top1 w8: U6.24 -406.16,183.17 -384.87,183.17 -378.04,190 -305.62,190 -302.98,192.64 U1.17
USB_DATA1_1: U1.26 U6.23 | length 276.8
  Top1 w8: U6.23 -386.67,163.21 -292,68.54 -292,23 -284.47,15.47 U1.26
USB_DATA2_1: U1.27 U6.22 | length 285.9
  Top1 w8: U6.22 -405.43,142.53 -384.37,142.53 -308,66.16 -308,5 -298.79,-4.21 U1.27
USB_DATA3_1: U1.29 U6.21 | length 293.8
  Top1 w8: U6.21 -395.2,123.84 -321.6,50.24 -321.6,-10.4 -288.42,-43.58 U1.29
USB_DATA4_1: U1.30 U6.20 | length 298.1
  Top1 w8: U6.20 -395.2,104.16 -337,45.95 -337,-22 -295.73,-63.27 U1.30
USB_DATA5_1: U1.33 U6.19 | length 465.3
  Top1 w8: U6.19 -395.2,84.47 -351.68,40.95 -351.68,-123.12 -298.8,-176 -148.4,-176 -146.64,-174.24 U1.33
USB_DATA6_1: U1.34 U6.18 | length 533
  Top1 w8: U6.18 -395.2,64.79 -364.68,34.26 -364.68,-128.5 -275.25,-217.94 -132.62,-217.94 -127.68,-213 -127.68,-174.23 U1.34
USB_DATA7_1: U1.57 U6.17 | length 661.5
  Top1 w8: U6.17 -395.59,45.1 -384,33.51 -384,28 v1(-383,27) ; v1(61,36) 160,36 180,56 214.66,56 217.66,53 U1.57
  Bottom2 w8: v1(-383,27) -370,14 39,14 v1(61,36)
USB_DIR_1: U1.10 U6.12 | length 847
  Top1 w8: v1(-509,-8) -508.92,-7.92 -508.92,21.35 U6.12 ; v1(-59,-56) -42,-39 -42,74.15 -28.53,87.63 U1.10
  Bottom2 w8: v1(-509,-8) -507,-10 -507,-36.46 -490.46,-53 -62,-53 v1(-59,-56)
USB_DM_CP_1: CON1.5 U3.5 | length 527.1
  Top1 w8: U3.5 -371.68,-238.32 v1(-351,-259) ; v1(-6,-339) 0,-339 0,-337.96 8.84,-329.12 8.84,-299 CON1.5 CON1.5@9.84,-278
  Bottom2 w8: v1(-351,-259) -351,-260.46 -266.46,-345 -12,-345 v1(-6,-339)
USB_DM_ST_1: CON1.7 U6.8 | length 1055.1
  Top1 w8: U6.8 -602.8,45.1 -637,10.9 -637,-52.8 -611.8,-78 -433.57,-78 -280.63,-230.94 43.1,-230.94 82.9,-270.74 82.9,-325.26 76.16,-332 55,-332 49.21,-326.21 CON1.7
USB_DP_CP_1: CON1.6 U3.4 | length 537.5
  Top1 w8: U3.4 -414,-258.5 v1(-380.5,-258.5) ; v1(22,-352) 28.53,-345.47 28.53,-299 CON1.6
  Bottom2 w8: v1(-380.5,-258.5) -376.96,-258.5 -277.46,-358 16,-358 v1(22,-352)
USB_DP_ST_1: CON1.8 U6.7 | length 990.5
  Top1 w8: U6.7 -612.76,64.79 -650,27.54 -650,-58.18 -617.18,-91 -438.95,-91 -286.02,-243.94 36.41,-243.94 67.9,-275.42 67.9,-297 CON1.8
USB_NXT_1: U1.11 U6.11 | length 854.5
  Top1 w8: v1(-529,-27) -528.76,-26.76 -528.76,21.2 U6.11 ; v1(-104.62,-72.38) -60,-27.75 -60,74.54 -48.21,86.33 U1.11
  Bottom2 w8: v1(-529,-27) -529,-32.84 -489.84,-72 -105,-72 v1(-104.62,-72.38)
USB_STP_1: U1.8 U6.13 | length 831
  Top1 w8: U6.13 -489.43,21.16 -489.43,-28.57 v1(-487.82,-30.18) ; v1(-20,-32) -17,-32 10.84,-4.16 U1.8
  Bottom2 w8: v1(-487.82,-30.18) -486,-32 v1(-20,-32)
VBUS_IN: C3.2 C4.2 C15.1 C16.1 C17.1 CON1.2 P1.2 R6.1 R8.2 R9.1 U2.1 U2.3 U3.7 U3.8 | length 3833.6
  Top1 w10: v1(-667,155) -666,154 -666,126 -691,101 -691,-44 -627,-108 -456,-108 -441,-123 -445.94,-127.94 -445.94,-165.5 U3.8 -446.94,-169 -445.94,-170 -421.86,-170 -416,-175.86 -416,-197.94 -415,-198.94 U3.7 -413.56,-198 -366,-198 -305,-259 -59,-259 -50,-268 -50,-272.87 -49.21,-273.66 CON1.2 -49.21,-483.21 ; U2.1@-327.56,-476.21 U2.1 -328.7,-480.76 -328.7,-532.3 C3.2 C15.1 C4.2 -259,-529 -259,-514 -252,-507 U2.3@-252,-487.85 ; U2.3 -252,-482.65 U2.3@-252,-487.85 ; P1.2@122,550 140.42,550 143.3,552.87 143.3,564.3 v1(144,565) v1@144,562 ; C17.1 C16.1 592,-225 547,-270 547,-426 400,-573 40.57,-573 -49.21,-483.21 ; C17.1@597,-164.78 612,-149.78 612,-96.11 628,-80.11 R8.2@628,-76 ; U2.3@-252,-487.85 -248.86,-491 -243.66,-491 -239.65,-495 -61,-495 -49.21,-483.21
  Bottom2 w10: v1(-667,155) -546,276 -546,397 -294,649 60,649 v1(144,565)
VCC_3V3: C1.2 C2.2 C6.2 C7.2 C8.2 C11.2 C20.2 C21.2 C22.1 C26.1 C27.1 C28.1 C29.1 C35.1 R1.2 R4.2 R11.2 S1.3 S1.4 U1.1 U1.19 U1.32 U1.48 U1.64 U2.5 U4.13 U4.14 U6.6 U6.16 U6.25 U6.30 U6.31 U7.3 U7.7 U7.8 | length 5895.3
  Top1 w10: v1(-636,67) -632.5,70.5 -632.5,85.5 C27.1@-632,86 ; v1(-619,-39) -619,-41 C22.1 ; U6.6 -591.86,84.76 -630.76,84.76 C27.1@-632,86 ; U6.31 -538.37,206.57 ; U6.30 -538.37,206.57 ; U6.16 -430.1,16.29 U6.16@-429.81,16 ; U6.25 -430.1,206.99 -429.1,208 v1(-381,208) C29.1@-356,208 ; v1(-412,17) -413,17 -414,16 U6.16@-429.81,16 ; C28.1 -429.81,2.81 U6.16@-429.81,16 ; v1(-367,169) -369.47,171.47 -361.47,171.47 C6.2 -333,143 -303,143 -283.77,162.23 -264.77,162.23 -262.23,159.68 -260.81,159.68 -254.74,153.61 -217.85,153.61 U1.19 -217.16,152.92 -201.7,152.92 -201,153.61 -175.39,153.61 -175,154 -108,87 -108,-41 -169.29,-102.29 -217.16,-102.29 U1.32 ; C11.2 -352,538 -300.68,538 -270.44,507.76 U7.8@-254.89,507.76 ; v1(-354.14,-322) -349.14,-327 C1.2 ; U2.5 -332.2,-363.26 -332.2,-328.8 C1.2 ; v1(-286,-142) C7.2 -270,-103 U1.32@-230.14,-103 ; v1(-275,-311) C2.2 C1.2 ; v1(-263,485) -263,499.65 U7.8@-254.89,507.76 ; U7.7 U7.8 ; R1.2@-150,391 -150,415 -140,425 -54.61,425 -43,436.61 ; C35.1 -57,632 -32.76,607.76 ; R4.2 -43,393 -43,436.61 ; v1(-22,444) -23.53,442.47 -37.14,442.47 -43,436.61 ; U7.3 -32.76,607.76 ; v1@133.53,314.47 148.64,299.36 U1.1 148.64,209.36 165.36,192.64 U1.64 221.16,192.64 222,193.47 v1(222,208) ; U1.48 148.64,-197.2 149.47,-198.03 v1(171,-198.03) 195.03,-198.03 199,-202 ; C8.2 206,-209 199,-202 ; U4.14 354.14,-54.82 328.18,-54.82 328,-55 v1(315.5,-55) C20.2 301,-53 301,-41 306.87,-35.13 354.14,-35.13 U4.13 ; R11.2 199,-202 ; v1(570,2) 571.53,3.53 577.98,3.53 C21.2 ; C27.1@-632,86 -647,101 -647,212 -624,235 -546,235 -538.37,227.37 -538.37,206.57 ; U7.8@-254.89,507.76 U7.8 ; U7.8 -76.69,507.76 -59,525.46 -59,581.53 -32.76,607.76
  Bottom2 w10: v1(-636,67) -619,50 -619,-222 -519,-322 v1(-354.14,-322) ; v1(-412,17) -412,95 -381,126 -381,171 ; v1(-367,169) -372,174 -379,174 -381,176 v1(-381,208) -326,263 -326,422 v1(-263,485) ; v1(-286,-142) -287.53,-143.53 -287.53,-164.53 -288,-165 -272,-181 -275,-184 v1(-275,-311) ; v1@-272,-308 -22.13,-308 11.53,-274.34 11.53,-198.47 33,-177 149.97,-177 v1(171,-198.03) 175.97,-198.03 217,-157 217,-96 258,-55 v1(315.5,-55) 336,-55 ; v1(-22,444) -20,446 47,446 70.44,422.56 S1.4 S1.3 99,379 99,325 106.47,317.53 123.47,317.53 v1(125,316) ; v1@225,208 317,208 363,162 363,-28 336,-55 ; v1(570,2) 513,-55 336,-55
pads on no net: CON1.0 H1.0 P1.SH1 P1.SH2 U1.2 U1.3 U1.4 U1.9 U1.14 U1.15 U1.16 U1.24 U1.25 U1.35 U1.36 U1.37 U1.39 U1.45 U1.54 U3.1 U3.2 U3.6 U3.10 U3.11 U3.12 U3.13 U3.14 U3.15 U3.16 U3.17 U3.18 U3.19 U3.20 U3.21 U3.22 U3.23 U3.24 U3.27 U3.28 U4.3 U4.6 U4.15 U4.19 U4.20 U4.21 U4.22 U4.29 U4.30 U6.3 U6.5 U6.10

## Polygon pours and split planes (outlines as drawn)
GND on Top1 "NONET_L01_P-001" (solid, remove dead copper, pour order 0): -768,820 834,820 834,-830 -768,-830
GND on Bottom2 "NONET_L01_P-001" (solid, remove dead copper, pour order 1): -766,822 834,822 834,-828 -766,-828

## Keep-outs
Keep-Out Layer:
  lines w10: -327.58,654.33 -292.13,716.15 -256.03,779.09 cw(c-221.88,759.5) -221.87,798.87 220.56,798.71 cw(c220.54,759.34) 254.64,779.01 290.88,716.22 326.65,654.22 ; -327.21,653.58 ccw(c0,-10) 326.51,653.93

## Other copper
Top1:
  text "ElectronBot-ENH" at -212,741 h30
  text "JSL   / 03.19.2022" at -148,-706 h30

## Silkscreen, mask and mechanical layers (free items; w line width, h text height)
Top Overlay:
  drawing of 343 lines, arcs and shapes, not listed
Mechanical 1:
  lines w10: -327.58,654.33 -292.13,716.15 -256.03,779.09 cw(c-221.88,759.5) -221.87,798.87 220.56,798.71 cw(c220.54,759.34) 254.64,779.01 290.88,716.22 326.65,654.22 ; -327.21,653.58 ccw(c0,-10) 326.51,653.93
